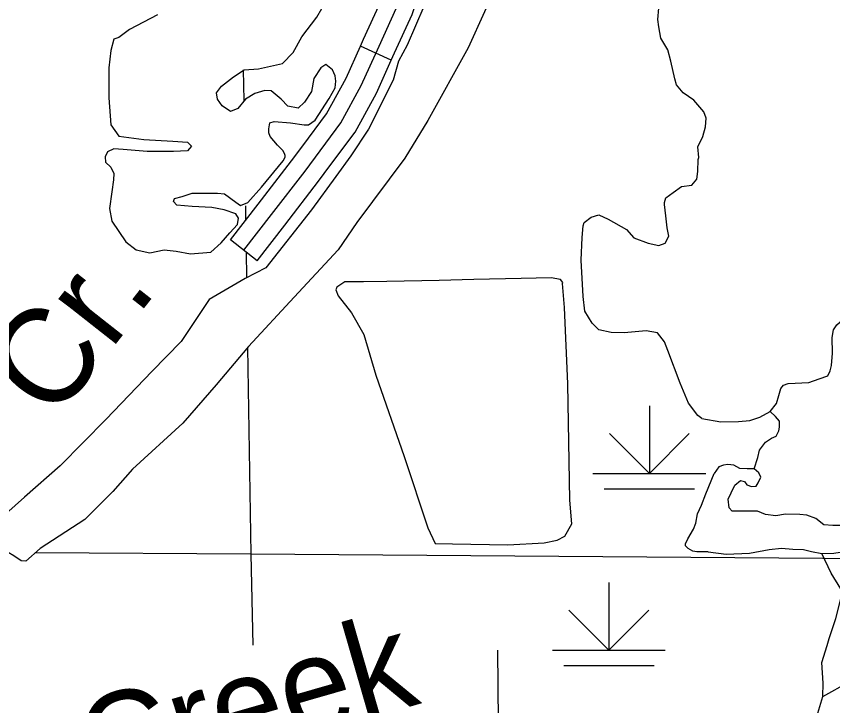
# Model space of a CAD drawing. Extents: x 22866 to 28196, y 1324810 to 1328105.
# Drawn here: x 25560.6 to 25647.4, y 1326140.7 to 1326214.1 of the extents above; entities that cross this region are included whole.
import ezdxf

# ---------------------------------------------------------------- set-up
doc = ezdxf.new("R2010")
doc.units = 0
for name, color, linetype in [('Level 31', 7, 'Continuous'), ('Level 34', 7, 'Continuous'), ('Level 35', 7, 'Continuous'), ('Level 44', 7, 'Continuous'), ('Level 45', 7, 'Continuous'), ('Level 5', 7, 'Continuous')]:
    doc.layers.add(name, color=color, linetype=linetype)

msp = doc.modelspace()

# ---------------------------------------------------------------- linework, layer by layer
at = {"layer": 'Level 31'}
msp.add_lwpolyline([(25584.779, 1326189.192), (25587.728, 1326192.987), (25591.309, 1326197.625), (25595.101, 1326202.755), (25597.278, 1326206.719), (25599.174, 1326210.936), (25600.999, 1326214.941), (25603.668, 1326223.094), (25605.844, 1326230.332), (25606.757, 1326235.182), (25606.983, 1326238.458)], dxfattribs=at)
at = {"layer": 'Level 34'}
msp.add_lwpolyline([(25611.867, 1326136.683), (25611.865, 1326138.998), (25611.817, 1326146.633)], dxfattribs=at)
at = {"layer": 'Level 35'}
for points in [[(25617.289, 1326235.756), (25614.939, 1326231.674), (25613.685, 1326228.377), (25612.43, 1326225.342), (25612.326, 1326223.668), (25612.744, 1326222.464), (25612.953, 1326221.208), (25612.535, 1326219.272), (25610.391, 1326214.563), (25608.666, 1326210.743)], [(25605.204, 1326219.28), (25603.939, 1326215.145), (25602.149, 1326211.024), (25601.229, 1326209.337), (25600.687, 1326207.288), (25598.056, 1326202.096), (25596.19, 1326199.238), (25594.568, 1326197.047), (25591.975, 1326193.511), (25587.124, 1326187.317), (25584.943, 1326186.205)], [(25584.148, 1326204.27), (25583.364, 1326203.956), (25582.475, 1326204.584), (25582.005, 1326205.265), (25581.9, 1326205.945), (25582.423, 1326206.677), (25583.678, 1326207.672), (25584.828, 1326208.404), (25586.344, 1326208.509), (25588.905, 1326209.084), (25590.055, 1326210.236), (25590.944, 1326211.91), (25592.565, 1326214.003), (25593.61, 1326215.887)], [(25575.627, 1326214.265), (25572.647, 1326212.695), (25571.497, 1326211.858), (25570.974, 1326211.648), (25570.661, 1326210.445), (25570.451, 1326208.613), (25570.451, 1326205.422), (25570.643, 1326202.542)], [(25620.784, 1326190.556), (25620.889, 1326191.78), (25620.993, 1326192.146), (25621.725, 1326192.722), (25622.561, 1326192.984), (25623.555, 1326192.513), (25625.489, 1326191.414), (25626.273, 1326190.524), (25627.789, 1326189.949), (25628.939, 1326189.687), (25629.619, 1326189.949), (25629.985, 1326190.681), (25629.828, 1326191.571), (25629.671, 1326192.879), (25629.514, 1326194.082), (25629.514, 1326194.292), (25629.671, 1326194.763), (25630.455, 1326195.338), (25631.344, 1326195.966), (25632.442, 1326196.123), (25632.965, 1326196.751), (25633.069, 1326197.588), (25633.121, 1326198.844), (25633.174, 1326199.053), (25633.069, 1326200.205), (25633.592, 1326201.303), (25633.906, 1326202.35), (25633.958, 1326203.24), (25633.697, 1326203.92), (25632.651, 1326205.176), (25631.501, 1326205.96), (25630.821, 1326206.798), (25630.612, 1326207.426), (25630.194, 1326209.309), (25629.88, 1326210.513), (25629.148, 1326211.769), (25628.939, 1326212.988), (25628.835, 1326213.757), (25628.939, 1326214.961)], [(25608.666, 1326210.743), (25604.379, 1326203.02), (25601.922, 1326198.991), (25596.799, 1326192.136), (25594.813, 1326189.258)], [(25594.59, 1326207.182), (25594.499, 1326207.776), (25594.238, 1326208.404), (25593.506, 1326208.98), (25592.983, 1326208.613), (25592.251, 1326207.462), (25591.99, 1326206.102), (25591.258, 1326204.951), (25590.578, 1326204.323), (25589.48, 1326204.532), (25588.748, 1326205.265), (25587.703, 1326206.154), (25587.023, 1326206.206), (25585.978, 1326205.893), (25584.985, 1326205.265), (25584.148, 1326204.27)], [(25591.678, 1326202.53), (25592.375, 1326203.059), (25593.874, 1326205.363), (25594.497, 1326206.489), (25594.59, 1326207.182)], [(25570.643, 1326202.542), (25571.497, 1326201.34), (25574.163, 1326200.974), (25577.248, 1326200.817), (25578.816, 1326200.712), (25579.234, 1326200.294), (25578.816, 1326199.77), (25577.3, 1326199.718), (25574.529, 1326199.718), (25571.968, 1326199.927), (25570.974, 1326199.98), (25570.295, 1326199.666), (25570.033, 1326199.142), (25570.086, 1326198.567), (25570.661, 1326198.044), (25570.974, 1326197.363), (25570.922, 1326196.683), (25570.765, 1326195.427)], [(25589.118, 1326199.497), (25588.958, 1326199.823), (25588.383, 1326200.398), (25587.598, 1326201.288), (25587.442, 1326201.706), (25587.442, 1326202.125), (25587.546, 1326202.753), (25588.017, 1326202.91), (25589.742, 1326202.753), (25591.206, 1326202.544), (25591.678, 1326202.53)], [(25584.441, 1326193.956), (25585.223, 1326194.273), (25586.68, 1326195.922), (25588.982, 1326198.713), (25589.193, 1326199.114), (25589.206, 1326199.288), (25589.118, 1326199.497)], [(25570.765, 1326195.427), (25570.504, 1326193.648), (25570.765, 1326192.288), (25572.229, 1326190.09), (25573.327, 1326189.253), (25574.79, 1326188.939), (25576.307, 1326189.253), (25577.613, 1326189.096), (25579.129, 1326188.834), (25581.273, 1326188.991), (25582.371, 1326189.985), (25583.315, 1326191.066), (25584.117, 1326191.933), (25584.223, 1326192.631), (25583.939, 1326193.073), (25582.684, 1326193.491), (25581.377, 1326193.753), (25579.286, 1326193.857), (25577.666, 1326194.014), (25577.3, 1326194.381), (25577.404, 1326194.695), (25578.241, 1326194.904), (25579.286, 1326195.27), (25580.698, 1326195.27), (25582.005, 1326195.27), (25582.737, 1326195.218), (25583.939, 1326194.328), (25584.441, 1326193.956)], [(25633.514, 1326171.276), (25633.069, 1326171.613), (25632.076, 1326172.922), (25631.187, 1326175.067), (25629.88, 1326178.52), (25629.514, 1326179.462), (25628.782, 1326180.404), (25627.58, 1326180.614), (25625.228, 1326180.404), (25623.868, 1326180.457), (25622.561, 1326180.718), (25621.83, 1326181.451), (25621.045, 1326182.707), (25620.889, 1326184.276), (25620.679, 1326188.149), (25620.784, 1326190.556)], [(25594.813, 1326189.258), (25590.16, 1326184.203), (25585.298, 1326178.971), (25581.848, 1326174.889), (25578.293, 1326170.808), (25572.961, 1326165.889), (25570.87, 1326163.534), (25567.89, 1326160.552), (25563.133, 1326157.464)], [(25584.943, 1326186.205), (25581.116, 1326183.942), (25578.136, 1326179.494), (25575, 1326176.302), (25570.138, 1326171.226), (25565.276, 1326166.255), (25561.46, 1326162.906)], [(25594.842, 1326184.363), (25596.253, 1326182.531), (25597.56, 1326180.229), (25598.815, 1326175.886), (25601.847, 1326167.252), (25604.356, 1326159.665), (25605.14, 1326157.99), (25606.97, 1326157.938), (25612.877, 1326157.833), (25616.746, 1326158.043), (25618.105, 1326158.357), (25618.941, 1326158.775), (25619.673, 1326160.083), (25619.464, 1326162.595), (25619.255, 1326174.996), (25618.889, 1326183.107), (25618.68, 1326185.671), (25618.732, 1326185.776), (25618.471, 1326186.09), (25617.478, 1326186.247), (25614.289, 1326186.194), (25609.27, 1326186.09), (25605.558, 1326185.985), (25600.017, 1326185.88), (25597.508, 1326185.828), (25595.521, 1326185.828), (25594.685, 1326185.252), (25594.58, 1326184.991), (25594.842, 1326184.363)], [(25647.293, 1326176.932), (25647.397, 1326178.258), (25647.345, 1326179.906), (25647.502, 1326180.717), (25647.868, 1326181.267), (25648.39, 1326181.738), (25649.049, 1326182.058)], [(25633.514, 1326171.276), (25635.504, 1326170.94), (25637.412, 1326170.967), (25638.615, 1326171.071), (25639.66, 1326171.438), (25640.758, 1326172.039), (25641.438, 1326172.903), (25641.673, 1326173.74), (25641.908, 1326174.472), (25642.169, 1326174.839), (25642.666, 1326175.022), (25644.888, 1326175.126), (25645.986, 1326175.519), (25646.9, 1326175.833), (25647.162, 1326176.382), (25647.293, 1326176.932)], [(25639.059, 1326165.943), (25639.451, 1326167.139), (25639.634, 1326167.924), (25640.261, 1326168.761), (25640.915, 1326169.18), (25641.411, 1326169.415), (25641.673, 1326169.965), (25641.751, 1326170.383), (25641.751, 1326171.011), (25641.333, 1326171.508), (25640.758, 1326172.039)], [(25637.621, 1326164.682), (25638.039, 1326164.583), (25638.275, 1326164.217), (25638.771, 1326164.06), (25639.268, 1326164.086), (25639.503, 1326164.426), (25639.765, 1326165.054), (25639.556, 1326165.525), (25639.059, 1326165.943), (25638.327, 1326165.943), (25637.543, 1326165.97), (25636.916, 1326166.336), (25636.262, 1326166.388), (25635.792, 1326166.336), (25635.321, 1326166.153), (25634.824, 1326165.42)], [(25634.18, 1326157.093), (25632.969, 1326157.1), (25632.55, 1326157.153), (25632.054, 1326157.467), (25631.766, 1326157.728), (25631.766, 1326157.964), (25632.002, 1326158.487), (25632.603, 1326159.507), (25632.864, 1326160.161), (25633.047, 1326161.129), (25633.465, 1326162.071), (25633.936, 1326163.275), (25634.824, 1326165.42)], [(25649.751, 1326160.211), (25648.782, 1326159.895), (25647.449, 1326159.895), (25646.482, 1326159.973), (25645.62, 1326160.653), (25644.679, 1326161.02), (25643.921, 1326161.072), (25642.405, 1326161.098), (25641.385, 1326160.941), (25640.261, 1326161.072), (25639.425, 1326161.412), (25638.432, 1326161.412), (25637.491, 1326161.412), (25636.733, 1326161.438), (25636.393, 1326161.778), (25636.288, 1326162.72), (25636.628, 1326163.374), (25637.02, 1326164.185), (25637.621, 1326164.682)], [(25561.46, 1326162.906), (25559.484, 1326161.159), (25558.386, 1326161.054), (25557.34, 1326161.316), (25554.099, 1326162.205), (25551.224, 1326162.571), (25545.421, 1326162.885), (25536.011, 1326162.781), (25525.399, 1326162.728), (25523.36, 1326162.414)], [(25646.252, 1326156.92), (25647.554, 1326156.97), (25648.678, 1326157.127), (25650.089, 1326157.781), (25650.351, 1326158.199), (25650.374, 1326158.459)], [(25561.61, 1326156.12), (25561.12, 1326156.135), (25560.336, 1326156.659), (25559.133, 1326157.391)], [(25563.133, 1326157.464), (25561.61, 1326156.12)], [(25634.18, 1326157.093), (25636.079, 1326156.839), (25638.562, 1326156.97), (25640.679, 1326157.336), (25641.96, 1326157.493), (25643.163, 1326157.388), (25644.313, 1326157.336), (25645.149, 1326157.127), (25646.252, 1326156.92)], [(25646.059, 1326130.773), (25645.939, 1326132.013), (25644.841, 1326135.415), (25644.579, 1326136.984), (25644.475, 1326138.24), (25645.834, 1326139.915), (25646.357, 1326141.694), (25646.409, 1326143.106), (25646.252, 1326145.304), (25646.827, 1326147.135), (25647.036, 1326147.868), (25647.768, 1326150.013), (25648.291, 1326152.106), (25648.291, 1326153.153), (25647.245, 1326154.827), (25646.252, 1326156.92)], [(25646.357, 1326141.694), (25649.18, 1326143.263), (25650.434, 1326143.787), (25652.369, 1326145.409), (25655.192, 1326147.711), (25656.76, 1326149.333), (25657.962, 1326150.327), (25659.008, 1326151.007), (25660.21, 1326151.06), (25661.36, 1326151.06), (25662.719, 1326150.851), (25663.817, 1326149.961), (25665.281, 1326149.595), (25666.431, 1326148.758), (25667.267, 1326147.659), (25667.372, 1326146.56), (25667.058, 1326145.984), (25666.379, 1326145.513), (25666.013, 1326145.461), (25665.438, 1326145.827)]]:
    msp.add_lwpolyline(points, dxfattribs=at)
at = {"layer": 'Level 44'}
for p, q in [((25627.924, 1326172.655), (25627.924, 1326165.454)), ((25627.924, 1326165.454), (25623.681, 1326169.697)), ((25627.924, 1326165.454), (25632.167, 1326169.697)), ((25621.923, 1326165.454), (25633.925, 1326165.454)), ((25623.123, 1326163.818), (25632.725, 1326163.818)), ((25623.616, 1326153.845), (25623.616, 1326146.644)), ((25623.616, 1326146.644), (25619.373, 1326150.887)), ((25623.616, 1326146.644), (25627.86, 1326150.887)), ((25617.615, 1326146.644), (25629.617, 1326146.644)), ((25618.815, 1326145.007), (25628.417, 1326145.007))]:
    msp.add_line(p, q, dxfattribs=at)
at = {"layer": 'Level 45'}
for p, q in [((25600.47, 1326209.429), (25597.186, 1326210.905)), ((25586.201, 1326188.087), (25583.358, 1326190.296))]:
    msp.add_line(p, q, dxfattribs=at)
for points in [[(25597.186, 1326210.905), (25597.534, 1326211.678), (25599.32, 1326215.597), (25601.599, 1326222.562)], [(25600.47, 1326209.429), (25600.814, 1326210.193), (25602.679, 1326214.286), (25605.021, 1326221.442)], [(25591.055, 1326200.31), (25593.581, 1326203.728), (25595.665, 1326207.523), (25597.186, 1326210.905)], [(25593.951, 1326198.17), (25596.621, 1326201.783), (25598.89, 1326205.915), (25600.47, 1326209.429)], [(25583.358, 1326190.296), (25586.305, 1326194.089), (25589.873, 1326198.71), (25591.055, 1326200.31)], [(25586.201, 1326188.087), (25589.152, 1326191.884), (25592.746, 1326196.54), (25593.951, 1326198.17)]]:
    msp.add_lwpolyline(points, dxfattribs=at)
at = {"layer": 'Level 5'}
for points in [[(25584.74, 1326208.398), (25584.789, 1326205.141)], [(25584.958, 1326193.939), (25584.982, 1326192.386)], [(25585.033, 1326188.994), (25585.074, 1326186.283)], [(25585.187, 1326178.851), (25585.52, 1326156.853)], [(25585.52, 1326156.853), (25562.612, 1326157.005)], [(25696.019, 1326154.343), (25651.053, 1326156.353), (25585.52, 1326156.853)], [(25585.52, 1326156.853), (25585.759, 1326147.149)]]:
    msp.add_lwpolyline(points, dxfattribs=at)

# ---------------------------------------------------------------- texts
at = {"layer": 'Level 35'}
for s, rotation, p in [('Cr.', 51.78746, (25564.553, 1326170.797)), ('Creek', 16.05502, (25569.008, 1326130.993))]:
    msp.add_text(s, height=10.1394, rotation=rotation, dxfattribs=at).set_placement(p)

doc.saveas('drawing.dxf')
